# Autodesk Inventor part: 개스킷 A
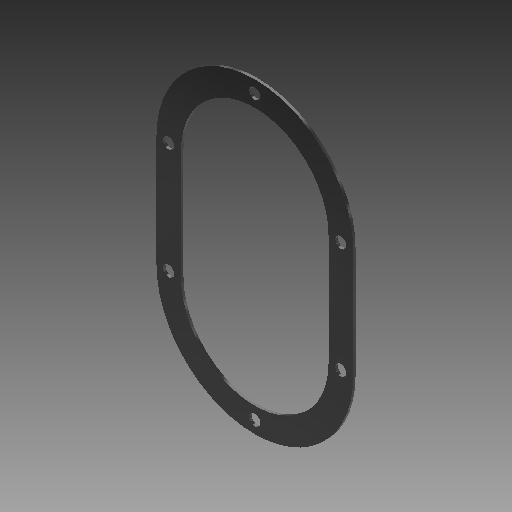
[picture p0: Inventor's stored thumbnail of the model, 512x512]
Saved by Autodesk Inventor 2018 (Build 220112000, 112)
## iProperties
Created: 2020-04
Part Number: 개스킷 A
Material: 고무
Document SubType Name: Modeling
Designer: mduedu
Density: 0.93 g/cm^3
Mass: 2.61813 g
Surface Area: 62.9733 cm^2
Volume: 2.81519 cm^3
Appearance: 고무 - 검은색 - 버전 1.1
Author: mduedu
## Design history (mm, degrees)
sketch "스케치1"
  geometry: L1 (-40, 0)-(-40, -45); L2 (40, 0)-(40, -45); A1 r 40 centre (0, 0) between (40, 0) and (-40, 0); A2 r 40 centre (0, -45) between (-40, -45) and (40, -45); 1 further point
  constraints: 4 end point, 4 point on circle, 4 tangent, 2 centre point, 1 coincident, 1 equal radius, 1 vertical alignment
  dimensions: "d0" = 80 diameter of A1; "d21" = 45 distance of point (0, 0) A2.centre
extrude "돌출1" new body sketch "스케치1" distance "d1" = 1; taper "d2" = 0 deg
sketch "스케치4"
  geometry: L1 (-30, 0)-(-30, -45); L2 (30, 0)-(30, -45); A1 r 30 centre (0, 0) between (30, 0) and (-30, 0); A2 r 30 centre (0, -45) between (-30, -45) and (30, -45); 1 further point
  constraints: 4 end point, 4 point on circle, 4 tangent, 2 centre point, 1 coincident, 1 equal radius, 1 vertical alignment
  dimensions: "d17" = 60 diameter of A1; "d24" = 45 distance of point (0, 0) A2.centre
extrude "돌출3" cut sketch "스케치4" extent not by distance; stored distance "d18" = 1; taper "d19" = 0 deg
sketch "스케치3"
  geometry: A1 r 35 centre (0, 0) between (0, 35) and (-35, 0); A2 r 35 centre (0, -45) between (-35, -45) and (0, -80); 3 further points
  constraints: 6 point on circle, 5 vertical alignment, 3 horizontal alignment, 2 centre point, 1 coincident, 1 equal radius
  dimensions: "d6" = 70 diameter of A1; "d28" = 45 distance of point (0, 0) A2.centre
hole "구멍1" sketch "스케치3" at (0, 35), (-35, 0), (35, 0), (35, -45), (-35, -45), (0, -80) diameter "d7" = 4.5; stored, may be unused: countersink angle "d11" = 90 deg, drill point angle "d13" = 118 deg; dims "d8" = 6, "d9" = 4, "d10" = 2, "d12" = 8
node "솔리드1"
